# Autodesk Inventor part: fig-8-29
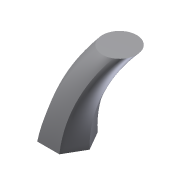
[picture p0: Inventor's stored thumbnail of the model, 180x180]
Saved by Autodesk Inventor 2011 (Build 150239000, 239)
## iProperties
Shininess: 77.0
Angle Display Precision: 2
Document Length Units: 11269
Document Angle Units: 11279
Document Time Units: 11290
Document Mass Units: 11283
Document Length Units Precision: 3
Document Angle Units Precision: 2
Created: 2001-12
Part Number: fig-8-29
Document SubType Name: Modeling
Designer: CADSoft
Density: 1 g/cm^3
Density: 0.0
Volumn: 0.0
Area: 0.0
PropertySet Name: Model Information
Control State: 0
Master: False
Checked Out: False
Author: CADSoft
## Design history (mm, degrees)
workplane "Work Plane3"
workplane "Work Plane4"
sketch "Sketch12"
  geometry: L1 (0, 10.598)-(9.178, -5.299); L2 (9.178, -5.299)-(-9.178, -5.299); L3 (-9.178, -5.299)-(0, 10.598); 1 further point
  constraints: 6 end point, 5 other
workplane "Work Plane5"
workplane "Work Plane6"
workplane "Work Plane7"
sketch "Sketch16"
  geometry: A1 r 72.799 centre (23.007, 110.594) between (0, 41.527) and (70, 54.995); 1 further point
  constraints: 2 point on circle, 1 centre point
loft "Loft5" sketch "Sketch16" dims "d57" = 0, "d58" = 90 deg, "d59" = 0, "d60" = 90 deg, "d61" = 0, "d62" = 90 deg
body "Solid2"
sketch "Sketch1"
  geometry: L1 (19.387, 0)-(9.693, -16.79); L2 (9.693, -16.79)-(-9.693, -16.79); L3 (-9.693, -16.79)-(-19.387, 0); L4 (-19.387, 0)-(-9.693, 16.79); L5 (-9.693, 16.79)-(9.693, 16.79); L6 (9.693, 16.79)-(19.387, 0); 1 further point
  constraints: 12 end point, 11 other
sketch "Sketch2"
  geometry: C1 r 15 at (23.06, 22.535)
  constraints: 1 centre point
